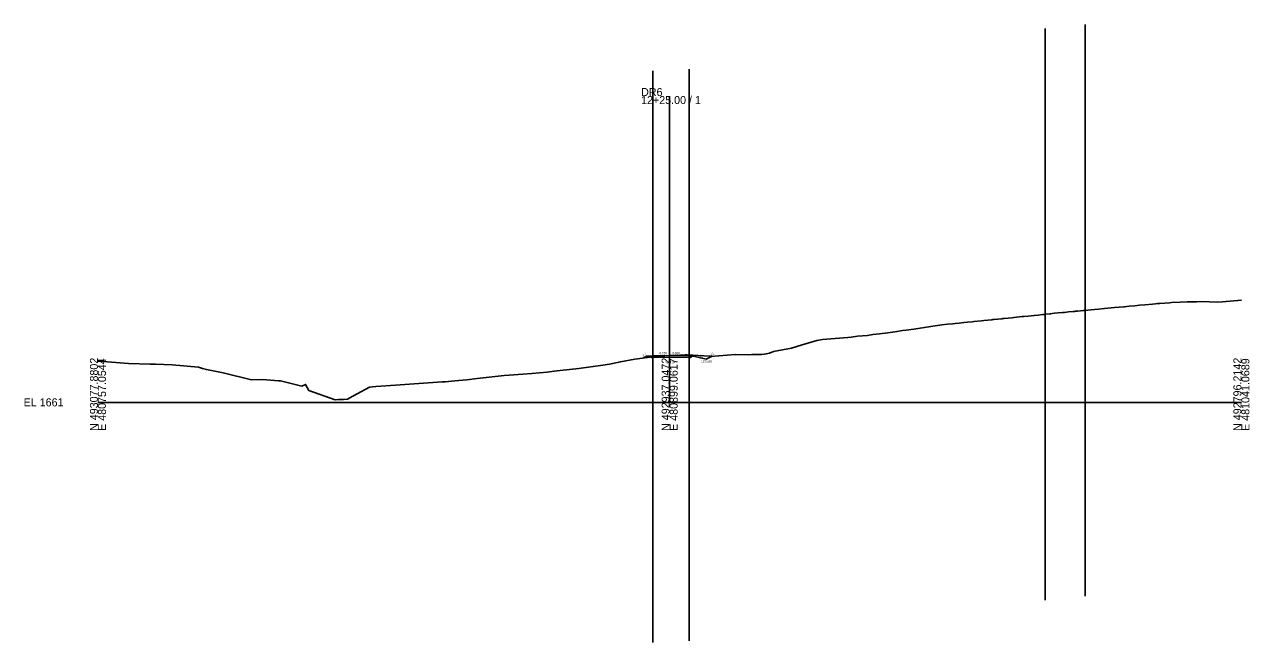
# Model space of a CAD drawing. Extents: x -26 to 403, y -88 to 5647.
# Drawn here: x -25.7 to 402.8, y 4416 to 4632.2 of the extents above; entities that cross this region are included whole.
import ezdxf

# ---------------------------------------------------------------- set-up
doc = ezdxf.new("R2010")
doc.units = 0
for name, color, linetype in [('Exist Cross Section Cell', 7, 'Continuous'), ('Exist XS Center Line Elevation Label', 7, 'Continuous'), ('Exist XS Ground Line', 7, 'Continuous'), ('Prop Road Sect_ Boring - Material (Outline)', 7, 'Continuous'), ('Prop XS Ditch Slope Text', 7, 'Continuous'), ('Prop XS Ditch Standard Text', 7, 'Continuous'), ('Prop XS Dump Level', 7, 'Continuous'), ('Prop XS Earthwork Shape', 7, 'Continuous'), ('Prop XS EOT Tick Mark', 7, 'Continuous'), ('Prop XS Finish Grade', 7, 'Continuous'), ('Prop XS Finish Grade Earthwork', 7, 'Continuous'), ('Prop XS Finish Grade Pavement', 7, 'Continuous'), ('Prop XS Hydro Typical Ditch Data', 7, 'Continuous'), ('Prop XS Pvmt Edge Slope', 7, 'Continuous'), ('Prop XS SE Text', 7, 'Continuous'), ('Prop XS Side Slope Text', 7, 'Continuous'), ('Prop XS Subgrade Earthwork', 7, 'Continuous'), ('Scratch_Level_7', 7, 'Continuous')]:
    doc.layers.add(name, color=color, linetype=linetype)

msp = doc.modelspace()

# ---------------------------------------------------------------- linework, layer by layer
at = {"layer": 'Exist Cross Section Cell'}
for p, q in [((200, 4500), (200, 4607.15)), ((0, 4500), (200, 4500)), ((200, 4500), (400, 4500))]:
    msp.add_line(p, q, dxfattribs=at)
at = {"layer": 'Exist XS Ground Line'}
msp.add_lwpolyline([(0, 4514.41), (1.78, 4514.3), (10.69, 4513.63), (18.25, 4513.4), (20.11, 4513.32), (25.93, 4513.18), (35.12, 4512.31), (36.58, 4511.87), (37.96, 4511.49), (43.85, 4510.31), (53.67, 4507.93), (57.62, 4508.03), (63.13, 4507.58), (63.85, 4507.53), (68.55, 4506.34), (71.38, 4505.61), (72.61, 4506.27), (73.76, 4504.1), (82.97, 4500.86), (84.11, 4500.94), (85.17, 4500.99), (85.85, 4501.04), (87.34, 4501.11), (89.18, 4502.12), (95.02, 4505.35), (96.1, 4505.42), (97.19, 4505.49), (104.05, 4505.99), (120.45, 4507.14), (121.51, 4507.21), (124.83, 4507.53), (129.07, 4507.85), (132.63, 4508.29), (142.15, 4509.38), (143.83, 4509.53), (148.62, 4509.87), (151.75, 4510.05), (157.15, 4510.51), (159.61, 4510.89), (161.68, 4511.1), (168.22, 4511.82), (176.6, 4513.06), (178.92, 4513.39), (182.75, 4514.19), (187.79, 4515.08), (194, 4515.98), (194.3, 4516.01), (194.9, 4516.06), (200, 4516.34), (203.63, 4516.55), (205.43, 4516.65), (206.14, 4516.63), (213.91, 4516.11), (214.33, 4516.09), (223.02, 4516.68), (227.67, 4516.61), (228.71, 4516.77), (232.1, 4516.74), (233.09, 4516.85), (233.8, 4516.93), (234.98, 4517.25), (236.29, 4517.77), (242.64, 4519.01), (246.36, 4520.11), (251.5, 4521.69), (253.41, 4522), (262.29, 4522.7), (263.54, 4522.85), (265.76, 4523.15), (269.18, 4523.42), (271.12, 4523.69), (273.45, 4524.01), (276.29, 4524.35), (278.77, 4524.71), (281.4, 4525.09), (282.78, 4525.26), (285.36, 4525.64), (291.4, 4526.54), (292.01, 4526.63), (294.48, 4527), (295.26, 4527.09), (297.17, 4527.3), (299.1, 4527.52), (299.84, 4527.59), (301.24, 4527.73), (302.1, 4527.82), (302.85, 4527.9), (304.22, 4528.04), (305.88, 4528.21), (306.37, 4528.26), (309.11, 4528.54), (309.88, 4528.62), (311.31, 4528.76), (312.71, 4528.91), (313.06, 4528.94), (313.4, 4528.98), (316.23, 4529.26), (316.59, 4529.29), (316.96, 4529.33), (318.39, 4529.48), (319.83, 4529.62), (320.45, 4529.68), (323.34, 4529.98), (323.66, 4530.01), (323.99, 4530.04), (325.46, 4530.2), (327.51, 4530.41), (328.88, 4530.55), (330.44, 4530.71), (331.04, 4530.78), (331.56, 4530.83), (333.06, 4530.98), (333.38, 4531.01), (333.76, 4531.05), (334.6, 4531.14), (335.88, 4531.26), (337.4, 4531.41), (338.08, 4531.48), (339.47, 4531.61), (341.11, 4531.77), (341.6, 4531.82), (341.98, 4531.86), (342.68, 4531.93), (343.75, 4532.03), (344.64, 4532.11), (345.11, 4532.16), (348.62, 4532.49), (350.19, 4532.63), (352.13, 4532.81), (355.64, 4533.14), (358.86, 4533.43), (359.16, 4533.46), (360.79, 4533.61), (362.68, 4533.78), (364.34, 4533.94), (366.2, 4534.11), (368.89, 4534.36), (370, 4534.46), (370.71, 4534.53), (371.48, 4534.59), (373.18, 4534.75), (374.88, 4534.87), (375.5, 4534.92), (378.62, 4535.08), (381.09, 4535.11), (384.27, 4535.21), (385.9, 4535.26), (391.79, 4535.1), (393.45, 4535.16), (400, 4535.72)], dxfattribs=at)
at = {"layer": 'Prop Road Sect_ Boring - Material (Outline)'}
for points in [[(194.14, 4516.27), (193.58, 4515.72), (193.11, 4516.19)], [(207.35, 4515.7), (207.82, 4516.17), (206.8, 4516.25)]]:
    msp.add_lwpolyline(points, close=True, dxfattribs=at)
at = {"layer": 'Prop XS Dump Level'}
for p, q in [((194.14, 4516.27), (200, 4516.39)), ((200, 4516.39), (206.8, 4516.25))]:
    msp.add_line(p, q, dxfattribs=at)
at = {"layer": 'Prop XS Earthwork Shape'}
for points in [[(193.41, 4515.89), (193.11, 4516.19), (192.14, 4516.11), (191.02, 4515.55)], [(193.41, 4515.89), (194, 4515.98), (194.3, 4516.01), (194.9, 4516.06), (200, 4516.34), (203.63, 4516.55), (205.43, 4516.65), (206.14, 4516.63), (213.91, 4516.11), (214.33, 4516.09), (214.88, 4516.13), (212.8, 4515.09), (208.8, 4516.09), (207.82, 4516.17), (207.35, 4515.7), (206.8, 4515.71), (200, 4515.84), (194.14, 4515.73), (193.58, 4515.72)]]:
    msp.add_lwpolyline(points, close=True, dxfattribs=at)
at = {"layer": 'Prop XS EOT Tick Mark'}
for p, q in [((194.14, 4516.27), (194.14, 4517.27)), ((206.8, 4516.25), (206.8, 4517.25))]:
    msp.add_line(p, q, dxfattribs=at)
at = {"layer": 'Prop XS Finish Grade'}
for p, q in [((194.14, 4516.27), (193.11, 4516.19)), ((206.8, 4516.25), (207.82, 4516.17))]:
    msp.add_line(p, q, dxfattribs=at)
at = {"layer": 'Prop XS Finish Grade Earthwork'}
for p, q in [((192.14, 4516.11), (191.02, 4515.55)), ((193.11, 4516.19), (192.14, 4516.11)), ((207.82, 4516.17), (208.8, 4516.09)), ((208.8, 4516.09), (212.8, 4515.09)), ((212.8, 4515.09), (214.88, 4516.13))]:
    msp.add_line(p, q, dxfattribs=at)
at = {"layer": 'Prop XS Finish Grade Pavement'}
for p, q in [((194.14, 4516.27), (200, 4516.39)), ((200, 4516.39), (206.8, 4516.25))]:
    msp.add_line(p, q, dxfattribs=at)
at = {"layer": 'Prop XS Hydro Typical Ditch Data'}
for p, q in [((208.8, 4516.09), (212.8, 4515.09)), ((212.8, 4515.09), (214.88, 4516.13))]:
    msp.add_line(p, q, dxfattribs=at)
at = {"layer": 'Prop XS Pvmt Edge Slope'}
for p, q in [((194.14, 4516.27), (193.58, 4515.72)), ((206.8, 4516.25), (207.35, 4515.7))]:
    msp.add_line(p, q, dxfattribs=at)
at = {"layer": 'Prop XS Subgrade Earthwork'}
for p, q in [((193.58, 4515.72), (193.11, 4516.19)), ((194.14, 4515.73), (193.58, 4515.72)), ((200, 4515.84), (194.14, 4515.73)), ((206.8, 4515.71), (200, 4515.84)), ((206.8, 4515.71), (207.35, 4515.7)), ((207.35, 4515.7), (207.82, 4516.17))]:
    msp.add_line(p, q, dxfattribs=at)
at = {"layer": 'Scratch_Level_7'}
for p, q in [((331.31, 4630.8), (331.31, 4430.8)), ((345.31, 4632.18), (345.31, 4432.18)), ((194.14, 4615.99), (194.14, 4415.99)), ((206.8, 4616.59), (206.8, 4416.59))]:
    msp.add_line(p, q, dxfattribs=at)

# ---------------------------------------------------------------- texts
at = {"layer": 'Exist Cross Section Cell'}
for s, p in [('12+25.00 / 1', (190, 4604.35)), ('DR6', (190, 4607.15)), ('EL 1661', (-26, 4498.6))]:
    msp.add_text(s, height=2.8, dxfattribs=at).set_placement(p)
for s, p in [('N 493077.8802', (0, 4490)), ('E 480757.0544', (2.8, 4490)), ('N 492937.0472', (200, 4490)), ('E 480899.0617', (202.8, 4490)), ('N 492796.2142', (400, 4490)), ('E 481041.0689', (402.8, 4490))]:
    msp.add_text(s, height=2.8, rotation=90, dxfattribs=at).set_placement(p)
at = {"layer": 'Exist XS Center Line Elevation Label'}
msp.add_text('1677.34', height=0.75, dxfattribs=at).set_placement((198.29, 4513.59))
at = {"layer": 'Prop XS Ditch Slope Text'}
for s, rotation, p in [('2:1', 26.5651, (190.77, 4515.91)), ('4:1', 345.9638, (210.34, 4516))]:
    msp.add_text(s, height=0.75, rotation=rotation, dxfattribs=at).set_placement(p)
at = {"layer": 'Prop XS Ditch Standard Text'}
msp.add_text('1676.09', height=0.75, dxfattribs=at).set_placement((211, 4513.9))
at = {"layer": 'Prop XS Dump Level'}
for p in [(192.14, 4516.07), (208.8, 4516.05)]:
    msp.add_text('Case1', height=0.04, dxfattribs=at).set_placement(p)
at = {"layer": 'Prop XS SE Text'}
for rotation, p in [(1.1458, (196.44, 4516.81)), (358.8542, (200.94, 4516.87))]:
    msp.add_text('0.020', height=0.75, rotation=rotation, dxfattribs=at).set_placement(p)
at = {"layer": 'Prop XS Side Slope Text'}
msp.add_text('2:1', height=0.75, rotation=26.5651, dxfattribs=at).set_placement((214.34, 4516.23))

doc.saveas('drawing.dxf')
